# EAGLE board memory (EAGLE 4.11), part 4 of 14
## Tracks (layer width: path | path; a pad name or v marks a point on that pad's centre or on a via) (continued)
-IOP4  (via drill 0.61) (continued)
  Bottom 0.254: v22.23,277.5 24.13,279.4 v45.72,279.4 | v161.93,347.35 161.29,346.71 134.62,346.71 133.99,347.35 97.79,347.35 93.98,343.54 60.33,343.54 58.42,345.44 v55.88,345.44 29.21,345.44 v28.57,346.08 | v401.95,104.14 403.23,102.87 405.13,102.87 405.76,103.5 414.65,103.5 415.29,102.87 417.83,102.87 418.46,103.5 427.36,103.5 427.99,102.87 432.44,102.87 433.07,102.23 E06.N2 | v347.35,146.69 v398.78,146.69 | v347.35,143.51 345.44,141.6 321.31,141.6 320.68,142.24 304.8,142.24 304.17,141.6 255.91,141.6 254,143.51 238.76,143.51 236.22,140.97 147.32,140.97 144.78,143.51 119.38,143.51 118.11,142.24 104.14,142.24 103.5,142.88 102.87,142.88 101.6,141.6 50.16,141.6 48.9,140.34 v19.68,140.34
-IOT  (via drill 0.61)
  Top 0.254: v259.08,6.35 259.08,15.24 F20.U2 | v307.98,7.62 307.98,92.71 v307.34,93.34 | v297.18,139.7 297.81,140.34 297.81,151.13 297.18,151.76 D17.U2
  Route3 0.254: v312.42,139.7 314.32,137.79 314.32,99.69 v313.06,98.42
  Bottom 0.254: v259.08,6.35 259.71,6.98 276.23,6.98 276.86,7.62 v307.98,7.62 | v307.34,93.34 311.15,97.16 313.06,97.16 | 313.06,97.16 314.96,97.16 315.6,96.52 323.85,96.52 327.02,99.69 327.02,102.87 329.56,102.87 332.74,106.04 340.36,106.04 344.17,109.85 353.06,109.85 353.69,109.22 362.58,109.22 367.03,113.66 369.57,113.66 E11.J2 | v312.42,139.7 v297.18,139.7 | 313.06,97.16 v313.06,98.42
-IR00  (via drill 0.61)
  Route2 0.254: v283.21,179.07 287.65,179.07 288.29,179.7 292.74,179.7 293.37,180.34 D17.J2
  Route3 0.254: v260.35,149.86 260.35,179.07 259.08,180.34 259.08,183.51 D20.H2
  Bottom 0.254: v260.35,149.86 255.91,149.86 D20.V2 | v283.21,179.07 282.57,179.7 275.59,179.7 274.95,179.07 266.06,179.07 265.43,179.7 262.89,179.7 262.25,179.07 261.62,179.07 259.08,181.61 259.08,183.51 D20.H2
-IR01  (via drill 0.61)
  Top 0.254: v295.27,177.16 295.27,188.59 296.55,189.86 D17.E2
  Route2 0.254: D20.S2 258.44,159.38 257.18,160.66 257.18,170.18 261.62,170.18 265.43,173.99 267.97,173.99 D19.L2
  Bottom 0.254: v295.27,177.16 294,175.89 288.29,175.89 287.65,176.53 278.76,176.53 274.95,172.72 269.88,172.72 268.61,173.99 D19.L2
-IR02  (via drill 0.61)
  Top 0.254: v287.02,147.32 292.1,147.32 292.1,170.81 | 292.1,170.81 296.55,175.26 296.55,177.16 D17.K2 | v290.19,180.97 292.1,179.07 292.1,170.81
  Bottom 0.254: v287.02,147.32 269.88,147.32 268.61,148.59 D19.V2 | v290.19,180.97 288.29,182.88 287.02,182.88 286.38,182.25 277.5,182.25 276.86,182.88 272.42,182.88 271.78,183.51 D19.H2
-IR03  (via drill 0.61)
  Top 0.254: v277.5,186.06 279.4,187.96 v279.4,206.38 | v358.14,207.64 355.6,210.19 355.6,232.41 v356.87,233.68 | v290.19,287.02 290.19,274.96 288.93,273.69 288.93,252.09 v290.19,250.82 | v383.54,132.08 384.18,131.44 384.18,125.73 385.44,124.46 E10.E2
  Route2 0.254: v328.93,205.1 330.2,206.38 356.87,206.38 v358.14,207.64
  Route3 0.254: v274.32,158.75 276.23,160.66 276.23,184.78 v277.5,186.06 | v356.87,233.68 358.77,235.59 358.77,242.57 357.5,243.84 C12.L2 | v290.19,287.02 288.93,288.29 288.93,292.74 285.75,295.91 285.75,321.31 281.31,325.75 281.31,326.39 282.57,327.66 282.57,342.27 285.12,344.81 285.12,346.71 283.21,348.62 283.21,357.5 283.85,358.14 A18.U2 | v290.19,250.82 288.93,249.56 288.93,220.34 290.19,219.07 v290.19,206.38 | v383.54,132.08 384.18,132.72 v384.18,156.84 | v366.39,160.66 365.12,161.92 365.12,177.16 358.77,183.51 358.77,207.01 v358.14,207.64
  Bottom 0.254: v274.32,158.75 271.78,158.75 D19.S2 | v279.4,206.38 280.04,205.74 290.19,205.74 | 290.19,205.74 309.25,205.74 309.88,205.1 314.32,205.1 314.96,205.74 328.3,205.74 v328.93,205.1 | 290.19,205.74 v290.19,206.38 | v384.18,156.84 377.19,156.84 373.38,160.66 v366.39,160.66
-IRCLR  (via drill 0.61)
  Top 0.254: v252.73,173.35 250.82,175.26 v250.82,187.96 | v27.3,166.37 27.3,162.56 D38.R2 | v39.37,236.22 38.1,234.95 v38.1,191.13
  Route2 0.254: v27.3,166.37 31.75,170.81 31.75,186.69 27.3,186.69 D38.F2 | v39.37,236.22 42.55,236.22 42.55,240.66 C37.M2
  Bottom 0.254: 256.54,163.19 257.18,163.83 264.16,163.83 265.43,162.56 267.97,162.56 D19.R2 | 256.54,163.19 255.91,162.56 D20.R2 | D19.F2 267.97,187.96 263.52,187.96 262.25,189.23 261.62,189.23 260.99,188.59 256.54,188.59 255.91,187.96 D20.F2 255.27,187.32 251.46,187.32 v250.82,187.96 246.38,192.41 237.49,192.41 233.68,188.59 224.79,188.59 224.16,189.23 215.26,189.23 214.63,188.59 212.09,188.59 211.46,189.23 202.56,189.23 201.93,188.59 199.39,188.59 198.75,189.23 189.87,189.23 189.23,188.59 186.69,188.59 186.06,189.23 178.44,189.23 177.8,188.59 173.99,188.59 173.35,189.23 164.47,189.23 163.83,188.59 161.29,188.59 160.66,189.23 151.76,189.23 151.13,188.59 148.59,188.59 147.96,189.23 139.06,189.23 138.43,188.59 135.89,188.59 135.25,189.23 126.36,189.23 125.73,188.59 123.19,188.59 122.56,189.23 113.67,189.23 113.03,188.59 110.49,188.59 109.86,189.23 100.97,189.23 100.33,188.59 97.79,188.59 97.16,189.23 88.27,189.23 84.45,185.42 76.2,185.42 72.39,189.23 62.87,189.23 62.23,188.59 59.69,188.59 59.05,189.23 50.16,189.23 49.53,188.59 46.99,188.59 46.35,189.23 40.01,189.23 v38.1,191.13 36.83,192.41 34.29,192.41 29.84,187.96 27.3,187.96 D38.F2 | 256.54,163.19 254,165.73 254,173.35 v252.73,173.35
-IRSH  (via drill 0.61)
  Top 0.254: 269.88,172.09 268.61,170.81 268.61,168.91 D19.N2 | 269.88,172.09 271.14,173.35 271.14,177.16 D19.K2 271.14,178.44 269.88,179.7 269.88,188.59 268.61,189.86 268.61,193.04 D19.D2 | 269.88,172.09 269.88,154.31 271.14,153.03 D19.U2 | v236.22,307.98 238.12,306.07 v238.12,275.59 | v248.92,274.32 250.82,272.42 v250.82,194.31
  Route2 0.254: v236.22,307.98 233.68,307.98 B22.M2
  Route3 0.254: v259.08,173.35 259.08,177.16 D20.K2
  Bottom 0.254: D20.U2 259.08,153.03 263.52,153.03 264.8,154.31 267.97,154.31 269.24,153.03 271.14,153.03 D19.U2 | 262.25,170.18 264.16,170.18 265.43,168.91 267.97,168.91 D19.N2 | 262.25,170.18 257.18,170.18 255.91,168.91 D20.N2 | 262.25,170.18 v259.08,173.35 | v238.12,275.59 238.76,274.96 242.57,274.96 243.21,274.32 v248.92,274.32 | v250.82,194.31 251.46,193.67 255.27,193.67 D20.D2 255.91,194.31 258.44,194.31 259.71,195.58 262.25,195.58 262.89,194.94 267.33,194.94 267.97,194.31 D19.D2
-ISZ  (via drill 0.61)
  Top 0.254: v242.57,222.88 241.3,224.16 241.3,286.39 241.94,287.02 241.94,290.83 243.21,290.83 244.47,289.56 245.75,289.56 B21.U2 | v262.25,55.25 260.35,53.34 260.35,43.18 259.08,41.91 F20.K2 | v296.55,160.66 296.55,164.47 D17.P2 | v341.63,220.34 340.36,219.07 340.36,208.91 v341,208.28 | v295.91,217.81 v295.91,208.28
  Route2 0.254: v341.63,220.34 344.81,220.34 345.44,220.98 351.15,220.98 351.79,220.34 360.68,220.34 364.49,224.16 368.94,224.16 369.57,224.79 C11.T2
  Route3 0.254: v295.91,217.81 297.18,219.07 298.45,219.07 298.45,176.53 295.27,173.35 295.27,169.54 296.55,168.28 296.55,165.73 D17.P2 | v262.25,55.25 273.05,66.04 276.23,66.04 276.23,153.03 v280.67,157.48
  Bottom 0.254: v242.57,222.88 248.28,217.17 295.27,217.17 v295.91,217.81 | v280.67,157.48 283.21,160.02 289.56,160.02 290.19,160.66 v296.55,160.66 | v341,208.28 340.36,208.91 326.39,208.91 325.75,209.55 312.42,209.55 311.15,208.28 v295.91,208.28
-JMP  (via drill 0.61)
  Top 0.254: 158.75,107.31 v156.84,109.22 | v158.75,71.12 158.75,107.31 | v233.04,71.75 238.12,66.67 238.12,34.29 v247.01,25.4 | 158.75,107.31 v158.75,146.05
  Route2 0.254: v268.61,147.32 282.57,147.32 289.56,154.31 292.74,154.31 293.37,154.94 D17.T2 | v331.47,118.74 325.12,125.09 316.87,125.09 316.23,125.73 313.69,125.73 313.06,125.09 304.17,125.09 300.36,128.91 299.08,128.91 v297.18,127
  Route3 0.254: v385.44,107.95 385.44,105.41 E10.M2 | v297.18,127 295.27,128.91 295.27,138.43 292.74,140.97 292.74,143.51 293.37,144.14 293.37,147.32 292.1,148.59 292.1,153.67 293.37,154.94 D17.T2
  Bottom 0.254: F16.R2 306.07,24.77 303.53,24.77 302.26,23.49 299.72,23.49 299.08,24.13 290.19,24.13 288.93,22.86 287.65,22.86 285.12,20.32 277.5,20.32 276.86,20.95 274.32,20.95 273.69,20.32 264.8,20.32 264.16,20.95 259.71,20.95 259.08,21.59 F20.S2 258.44,22.86 254.63,22.86 253.37,24.13 252.09,24.13 251.46,23.49 248.92,23.49 v247.01,25.4 | v156.84,109.22 150.5,109.22 149.86,109.85 145.41,109.85 144.78,110.49 E29.K2 | v158.75,71.12 188.59,71.12 189.87,69.85 191.13,69.85 193.04,71.75 210.82,71.75 211.46,72.39 230.5,72.39 231.78,71.12 232.41,71.12 v233.04,71.75 | v268.61,147.32 240.66,147.32 236.85,151.13 227.97,151.13 227.33,150.5 224.79,150.5 224.16,151.13 215.26,151.13 214.63,150.5 212.09,150.5 211.46,151.13 202.56,151.13 201.93,150.5 199.39,150.5 198.75,151.13 196.22,151.13 190.5,145.41 159.38,145.41 v158.75,146.05 | v385.44,107.95 384.18,109.22 377.19,109.22 374.01,112.39 372.75,112.39 371.48,113.66 371.48,115.57 366.39,115.57 362.58,119.38 356.24,119.38 353.06,122.55 350.52,122.55 345.44,117.47 345.44,115.57 339.09,115.57 338.45,116.2 334.01,116.2 v331.47,118.74
-JMS  (via drill 0.61)
  Top 0.254: v255.27,275.59 255.27,283.85 254,285.12 254,292.74 255.27,294 255.27,297.81 B20.R2 | v260.35,9.52 v260.35,13.97 260.35,26.67 259.08,27.94 F20.P2 | v317.5,9.52 317.5,36.2 318.77,37.46 F15.L2 | v142.88,62.87 142.88,106.04 141.6,107.31 E29.L2 | v189.23,156.21 187.32,154.31 v187.32,147.95 | v162.56,147.32 161.93,146.69 v161.93,114.3
  Route2 0.254: v281.31,160.02 287.65,160.02 288.29,160.66 295.27,160.66 296.55,159.38 D17.S2
  Route3 0.254: v301.62,273.05 301.62,227.97 304.8,224.79 304.8,187.96 301.62,184.78 301.62,161.29 v300.36,160.02 | v142.88,62.87 142.88,59.69 v189.87,12.7
  Bottom 0.254: v255.27,275.59 255.91,276.23 269.24,276.23 270.51,274.96 299.72,274.96 v301.62,273.05 | v300.36,160.02 297.81,160.02 297.18,159.38 D17.S2 | v260.35,9.52 306.07,9.52 306.7,10.16 316.87,10.16 v317.5,9.52 | v189.87,12.7 192.41,10.16 201.29,10.16 201.93,10.79 213.36,10.79 217.17,14.61 226.06,14.61 226.69,13.97 227.33,13.97 227.97,14.61 234.31,14.61 234.95,15.24 238.12,15.24 239.4,13.97 248.28,13.97 248.92,14.61 251.46,14.61 252.09,13.97 v260.35,13.97 | v281.31,160.02 278.13,156.84 275.59,156.84 274.95,157.48 266.06,157.48 262.25,153.67 253.37,153.67 252.73,154.31 250.19,154.31 249.56,153.67 248.28,153.67 245.11,156.84 237.49,156.84 236.85,157.48 227.97,157.48 227.33,156.84 224.79,156.84 224.16,157.48 215.26,157.48 214.63,156.84 212.09,156.84 211.46,157.48 202.56,157.48 201.93,156.84 199.39,156.84 198.75,157.48 190.5,157.48 v189.23,156.21 | v187.32,147.95 186.06,146.69 163.19,146.69 v162.56,147.32 | v161.93,114.3 161.93,112.39 151.76,112.39 151.13,113.03 148.59,113.03 147.96,112.39 143.51,112.39 141.6,110.49 141.6,108.58 E29.L2
-L  (via drill 0.61)
  Route2 0.254: v446.4,234.31 439.42,241.3 438.79,241.3 421.64,258.44 421,258.44 421,262.89 C07.D2 | v454.02,182.88 454.02,176.53 452.12,176.53 447.68,172.09 447.68,156.84 445.13,156.84 437.51,149.22 437.51,139.7 441.32,135.89 v441.32,111.76
  Route3 0.254: v446.4,234.31 447.68,233.04 447.68,227.33 454.02,220.98 454.02,205.74 452.75,204.47 452.75,201.93 454.02,200.66 v454.02,182.88 | v441.32,111.76 441.32,72.39 438.15,69.22 438.15,55.88 436.88,54.61 F06.E2
  Bottom 0.254: F03.H2 474.35,46.99 473.07,45.72 466.09,45.72 462.28,49.53 455.93,49.53 452.75,52.7 443.87,52.7 443.23,52.07 441.96,52.07 440.69,53.34 436.88,53.34 F06.E2
-LAS  (via drill 0.61)
  Top 0.254: v257.81,296.55 257.18,297.18 257.18,311.79 256.54,312.42 256.54,316.23 257.18,316.87 257.18,323.85 259.08,325.75 259.08,326.39 B20.E2
  Route2 0.254: v481.33,306.07 474.98,299.72 467.36,299.72 v465.45,301.62 | v433.07,300.36 426.08,293.37 415.29,293.37 411.48,297.18 402.59,297.18 401.95,296.55 393.06,296.55 392.43,297.18 389.89,297.18 389.25,296.55 387.99,296.55 386.08,298.45 381,293.37 377.19,293.37 376.56,294 367.67,294 367.03,293.37 364.49,293.37 363.86,294 357.5,294 356.87,293.37 354.33,293.37 351.15,290.2 342.26,290.2 341.63,290.83 339.09,290.83 335.28,287.02 326.39,287.02 325.75,287.66 316.87,287.66 316.23,287.02 313.69,287.02 313.06,287.66 304.17,287.66 303.53,287.02 302.26,287.02 295.91,293.37 288.29,293.37 287.65,294 278.76,294 278.13,293.37 275.59,293.37 274.32,294.64 271.78,294.64 B19.S2
  Bottom 0.254: v257.81,296.55 262.25,296.55 262.89,297.18 269.88,297.18 271.14,295.91 B19.S2 | v481.33,306.07 487.68,306.07 491.49,309.88 495.94,309.88 496.57,310.52 B01.L2 | v465.45,301.62 464.82,300.99 463.55,300.99 462.92,300.36 456.56,300.36 455.93,299.72 453.39,299.72 452.75,300.36 445.13,300.36 444.5,299.72 440.69,299.72 440.06,300.36 v433.07,300.36
-LCIF  (via drill 0.61)
  Route3 0.254: v55.24,93.98 58.42,97.16 58.42,98.42 69.85,109.85 69.85,205.74 66.67,208.91 66.67,294.64 63.5,297.81 v63.5,307.34
  Bottom 0.254: v55.24,93.98 48.26,86.99 40.01,86.99 40.01,83.18 E37.V2 | v63.5,307.34 65.41,309.25 73.66,309.25 74.93,310.52 77.47,310.52 B34.L2
-LD  (via drill 0.61)
  Top 0.254: v361.95,342.27 361.95,397.51 358.14,401.32 352.43,401.32 352.43,399.42 349.25,396.24 347.98,396.24 A13.E2 347.35,397.51 346.07,398.78 346.07,400.69 335.28,411.48 v334.64,411.48 | 28.57,223.52 27.3,224.79 C38.T2 | 28.57,223.52 v28.57,209.55 | v137.79,209.55 139.7,207.64 v139.7,168.28 | v62.23,317.5 60.33,315.6 60.33,297.18 v55.88,292.74 | v34.92,285.12 33.66,283.85 v33.66,273.69 | v26.67,234.95 28.57,233.04 28.57,223.52 | v250.82,408.94 250.82,412.75 253.37,415.29 252.09,416.56 196.85,416.56 196.85,408.31 193.68,405.13 v193.68,393.06 | v128.91,349.89 120.65,341.63 120.65,338.46 v112.39,330.2
  Route2 0.254: v62.23,317.5 63.5,318.77 66.67,318.77 67.94,320.04 B35.H2 68.58,321.31 71.12,321.31 75.56,325.75 84.45,325.75 85.09,325.12 87.63,325.12 88.27,325.75 97.16,325.75 97.79,325.12 101.6,325.12 108.58,332.11 110.49,332.11 v112.39,330.2 | v33.66,273.69 25.4,265.43 25.4,234.95 v26.67,234.95 | v193.68,393.06 193.68,386.08 186.69,386.08 182.88,382.27 173.99,382.27 173.35,382.91 164.47,382.91 163.83,382.27 161.29,382.27 160.66,382.91 158.12,382.91 154.94,379.73 154.31,379.73 v152.4,377.83
  Route3 0.254: v343.54,339.73 336.55,332.74 336.55,328.93 335.28,327.66 B14.E2 | v334.64,411.48 327.66,418.47 260.35,418.47 260.35,417.83 254,411.48 254,408.94 252.73,407.67 250.82,407.67 v250.82,408.94 | v152.4,377.83 152.4,377.19 128.91,353.7 v128.91,349.89
  Bottom 0.254: v343.54,339.73 346.07,342.27 v361.95,342.27 | v28.57,209.55 29.21,208.91 36.2,208.91 36.83,208.28 67.31,208.28 68.58,209.55 74.3,209.55 75.56,208.28 96.52,208.28 98.42,210.19 113.67,210.19 114.3,209.55 v137.79,209.55 | v139.7,168.28 139.7,165.73 144.15,165.73 D29.P2 | v55.88,292.74 53.98,290.83 48.26,290.83 44.45,287.02 38.73,287.02 36.83,285.12 v34.92,285.12
-LP  (via drill 0.61)
  Top 0.254: v57.15,356.24 57.15,394.97 55.88,396.24 A36.E2 | v273.05,352.43 273.05,382.27 271.78,383.54 A19.K2 271.14,384.81 271.14,388.62 269.88,389.89 v269.88,415.29 | v343.54,351.79 342.9,352.43 342.9,360.05 344.17,361.31 A13.T2 | v328.93,350.52 328.93,346.08 330.2,344.81 330.2,294 331.47,292.74 B14.T2 | v88.27,400.05 104.14,415.93 146.69,415.93 146.69,414.66 v147.96,413.39
  Bottom 0.254: 57.15,353.7 152.4,353.7 153.67,354.97 A28.V2 | 57.15,353.7 41.27,353.7 40.01,354.97 A37.V2 | v57.15,356.24 57.15,353.7 | B19.T2 268.61,292.74 273.05,292.74 274.32,294 276.86,294 277.5,293.37 286.38,293.37 287.02,294 289.56,294 293.37,290.2 300.36,290.2 304.17,294 314.96,294 315.6,293.37 324.49,293.37 325.12,294 326.39,294 328.3,292.1 331.47,292.1 B14.T2 | v273.05,352.43 290.83,352.43 294,349.25 323.85,349.25 324.49,349.89 328.93,349.89 | 328.93,349.89 339.73,349.89 341.63,351.79 v343.54,351.79 | 328.93,349.89 v328.93,350.52 | v88.27,400.05 86.36,398.15 83.82,398.15 83.19,398.78 74.3,398.78 73.66,398.15 71.12,398.15 70.48,398.78 61.59,398.78 60.96,398.15 56.52,398.15 55.88,397.51 A36.E2 | v147.96,413.39 154.31,413.39 155.57,414.66 161.93,414.66 162.56,415.29 192.41,415.29 193.68,416.56 252.09,416.56 253.37,415.29 v269.88,415.29
-LPA  (via drill 0.61)
  Top 0.254: v27.3,328.3 27.3,324.49 B38.F2 | v201.93,392.43 198.75,395.61 v198.75,398.15 | v69.22,388.62 63.5,382.91 63.5,376.56 64.77,375.29 A35.N2
  Route2 0.254: v27.3,328.3 28.57,329.56 28.57,334.01 64.14,369.57 64.77,369.57 64.77,374.02 A35.N2 | v179.71,401.96 179.07,401.32 173.99,401.32 173.35,401.96 164.47,401.96 160.66,398.15 151.76,398.15 142.24,407.67 137.16,407.67 133.35,411.48 92.08,411.48 v69.22,388.62
  Bottom 0.254: B38.F2 26.67,323.22 26.67,320.04 25.4,318.77 25.4,315.6 35.56,315.6 36.2,316.23 45.09,316.23 45.72,315.6 48.26,315.6 48.9,316.23 57.78,316.23 58.42,315.6 60.96,315.6 61.59,316.23 64.77,316.23 66.04,314.96 67.94,314.96 B35.K2 | v201.93,392.43 208.28,392.43 215.26,385.45 224.16,385.45 227.97,389.25 236.85,389.25 237.49,388.62 240.03,388.62 240.66,389.25 249.56,389.25 250.19,388.62 254.63,388.62 255.27,387.99 A20.J2 | v198.75,398.15 189.87,398.15 186.06,401.96 v179.71,401.96
-LPC  (via drill 0.61)
  Top 0.254: E05.U2 448.94,86.36 447.68,87.63 447.68,89.53 446.4,90.8 446.4,94.61 E05.R2 | C40.M2 5.08,241.94 6.35,243.2 6.35,276.86 5.08,278.13 5.08,287.02 6.35,288.29 6.35,366.4 5.08,367.67 5.08,370.84 A40.P2
  Route2 0.254: v337.82,85.72 335.92,83.82 328.93,83.82 325.75,80.64 318.13,80.64 311.15,87.63 304.17,87.63 295.27,96.52 288.29,96.52 281.94,102.87 275.59,102.87 274.95,103.5 266.06,103.5 265.43,102.87 264.16,102.87 v259.08,107.95 | v234.31,103.5 233.68,102.87 224.79,102.87 224.16,103.5 217.81,103.5 214.63,106.68 212.09,106.68 211.46,106.04 210.82,106.04 209.55,107.31 209.55,109.85 207.01,109.85 170.81,146.05 160.66,146.05 153.67,153.03 152.4,153.03 151.13,154.31 148.59,154.31 v142.88,148.59 | v71.75,152.4 53.98,170.18 53.98,201.29 46.99,201.29 8.26,240.03 5.71,240.03 5.08,240.66 C40.M2
  Route3 0.254: v408.31,90.8 404.5,94.61 v404.5,95.25
  Bottom 0.254: v408.31,90.8 415.93,90.8 422.27,84.45 427.36,84.45 427.99,83.82 430.53,83.82 431.17,84.45 440.06,84.45 440.69,83.82 447.68,83.82 448.94,85.09 E05.U2 | v404.5,95.25 402.59,93.34 395.61,93.34 392.43,90.17 390.52,90.17 387.35,93.34 380.37,93.34 379.73,93.98 377.19,93.98 376.56,93.34 367.67,93.34 367.03,93.98 365.76,93.98 363.22,91.44 361.95,91.44 360.68,90.17 351.79,90.17 351.15,90.8 343.54,90.8 338.45,85.72 v337.82,85.72 | v259.08,107.95 257.81,109.22 252.73,109.22 246.38,102.87 237.49,102.87 236.85,103.5 v234.31,103.5 | v142.88,148.59 141.6,147.32 100.33,147.32 99.69,146.69 82.55,146.69 78.74,150.5 73.66,150.5 v71.75,152.4
-LSH  (via drill 0.61)
  Top 0.254: F03.D2 471.81,56.52 473.07,55.25 473.07,46.36 474.35,45.09 474.35,41.91 F03.K2 | v160.02,300.99 161.93,302.9 161.93,310.52 165.1,313.69 v165.1,314.33 | v392.43,161.29 390.52,163.19 390.52,189.23 v389.25,190.5
  Route2 0.254: v457.2,137.16 457.2,140.34 450.85,140.34 v443.23,147.95 | v404.5,155.57 402.59,153.67 400.05,153.67 v392.43,161.29 | v393.7,229.23 388.62,234.31 387.35,234.31 386.08,233.04 379.1,233.04 372.75,239.39 366.39,239.39 v360.05,245.75 | v185.42,314.33 183.51,312.42 173.99,312.42 172.72,313.69 170.18,313.69 B27.K2
  Route3 0.254: v457.2,137.16 457.2,81.91 466.73,72.39 466.73,57.79 471.17,57.79 F03.D2 | v389.25,190.5 390.52,191.77 390.52,198.12 392.43,200.03 393.7,200.03 393.7,199.39 394.33,198.75 396.88,198.75 396.88,199.39 400.05,202.56 400.05,212.72 398.78,214 398.78,217.81 400.05,219.07 400.05,222.88 v393.7,229.23 | v360.05,245.75 355.6,250.19 355.6,278.77 358.77,281.94 358.77,312.42 351.79,319.41 351.79,320.68 349.25,323.22 349.25,350.52 347.98,351.79 347.98,356.87 349.25,358.14 349.25,372.75 v337.82,384.18 | v288.93,386.72 287.65,385.45 278.76,385.45 274.95,389.25 266.06,389.25 262.25,385.45 257.18,385.45 257.18,387.99 249.56,395.61 240.66,395.61 233.68,388.62 225.43,388.62 225.43,384.81 213.36,372.75 203.2,372.75 203.2,363.22 200.03,360.05 200.03,346.71 187.32,334.01 187.32,328.3 184.15,325.12 184.15,315.6 v185.42,314.33
  Bottom 0.254: v160.02,300.99 158.75,299.72 149.22,299.72 142.88,306.07 137.79,306.07 137.16,306.71 132.72,306.71 132.08,307.34 B30.M2 | v165.1,314.33 169.54,314.33 B27.K2 | v443.23,147.95 434.34,156.84 427.99,156.84 427.36,157.48 418.46,157.48 414.65,153.67 412.12,153.67 408.94,156.84 405.76,156.84 v404.5,155.57 | v337.82,384.18 335.92,386.08 326.39,386.08 325.75,385.45 316.87,385.45 316.23,386.08 313.69,386.08 310.51,382.91 306.7,382.91 303.53,386.08 302.26,386.08 299.72,383.54 298.45,383.54 297.81,382.91 294,382.91 290.19,386.72 v288.93,386.72
-MA00  (via drill 0.61)
  Top 0.254: v215.9,55.25 214.63,56.52 214.63,58.42 215.9,59.69 v215.9,76.83 v215.9,82.55 | v316.87,78.1 317.5,78.74 317.5,97.79 | 317.5,97.79 317.5,112.39 318.77,113.66 E15.J2 | v224.16,146.05 223.52,145.41 223.52,135.25 222.25,133.99 222.25,114.3 v220.98,113.03 | 317.5,97.79 v318.13,97.79
  Route2 0.254: v318.13,97.79 321.94,97.79 E15.P2
  Route3 0.254: v242.57,146.05 244.47,147.95 244.47,188.59 245.75,189.86 D21.E2 | v220.98,113.03 222.25,111.76 222.25,90.8 215.9,84.45 v215.9,82.55
  Bottom 0.254: v215.9,55.25 215.26,55.88 214,55.88 213.36,55.25 208.91,55.25 208.28,54.61 F24.E2 | v215.9,76.83 216.53,76.2 264.8,76.2 266.06,74.93 267.33,76.2 267.33,76.83 283.85,76.83 285.12,78.1 v316.87,78.1 | v224.16,146.05 v242.57,146.05
-MA00B  (via drill 0.61)
  Top 0.254: v382.9,28.58 382.9,31.12 F10.N2 | v386.71,29.84 390.52,26.03 390.52,12.06 v387.35,8.89 | v298.45,4.44 291.46,11.43 v290.83,11.43 | v266.7,12.06 263.52,15.24 263.52,27.94 254,37.46 254,43.82 v252.09,45.72
  Route2 0.254: v382.9,28.58 384.18,29.84 v386.71,29.84 | v387.35,8.89 386.71,9.52 373.38,9.52 367.67,3.81 340.36,3.81 339.73,4.44 339.09,4.44 337.82,3.17 299.72,3.17 v298.45,4.44 | v252.09,45.72 245.75,52.07 237.49,52.07 231.14,58.42 224.79,58.42 220.98,62.23 212.09,62.23 211.46,61.59 202.56,61.59 198.75,65.41 192.41,65.41 189.23,68.58 166.37,68.58 165.74,67.94 164.47,67.94 162.56,69.85 137.16,69.85 134.62,72.39 116.2,72.39 v90.17,98.42 | v88.27,257.18 v71.75,273.69
  Route3 0.254: v290.83,11.43 288.29,11.43 287.02,10.16 266.7,10.16 v266.7,12.06 | v90.17,98.42 88.9,99.69 88.9,182.25 92.08,185.42 92.08,253.36 v88.27,257.18 | v71.75,273.69 69.85,275.59 69.85,302.26 66.67,305.44 66.67,359.41 65.41,360.68 65.41,361.31 A35.T2
-MA01  (via drill 0.61)
  Top 0.254: v226.69,49.53 228.6,51.44 v228.6,67.94 | v299.72,69.22 302.89,72.39 v302.89,74.29 | v319.4,73.66 319.4,80.64 320.68,81.91 320.68,86.36 319.4,87.63 319.4,88.27 E15.T2 | v309.88,119.38 309.88,123.19 E16.E2 | v239.4,180.97 241.3,179.07 v241.3,142.24 | v304.8,123.82 v304.8,140.97
  Route3 0.254: v252.73,68.58 255.27,68.58 v255.27,69.22 | v309.88,119.38 311.15,118.11 311.15,99.06 318.77,91.44 318.77,89.53 E15.T2
  Bottom 0.254: v226.69,49.53 226.06,48.9 223.52,48.9 222.88,49.53 214,49.53 213.36,48.9 208.91,48.9 208.28,48.26 F24.H2 | v228.6,67.94 229.24,68.58 238.12,68.58 238.76,69.22 252.09,69.22 v252.73,68.58 | v255.27,69.22 256.54,70.48 295.91,70.48 297.18,69.22 v299.72,69.22 | v302.89,74.29 303.53,73.66 310.51,73.66 311.15,73.02 318.77,73.02 v319.4,73.66 | v239.4,180.97 240.03,180.97 241.3,182.25 244.47,182.25 245.75,183.51 D21.H2 | v241.3,142.24 254,142.24 255.27,140.97 v304.8,140.97 | v304.8,123.82 309.25,123.82 E16.E2
-MA01B  (via drill 0.61)
  Top 0.254: v22.23,319.41 22.23,367.03 v24.13,368.94
  Route2 0.254: v290.19,45.72 283.85,52.07 275.59,52.07 274.95,52.7 268.61,52.7 267.97,52.07 264.16,52.07 260.35,55.88 254,55.88 235.59,74.29 211.46,74.29 v210.19,75.56 | v175.9,76.83 162.56,76.83 161.93,76.2 126.36,76.2 v81.28,121.28 | v67.94,250.19 34.29,283.85 33.02,283.85 v23.5,293.37
  Route3 0.254: v382.27,47.62 382.27,45.09 F10.J2 | v81.28,121.28 79.38,123.19 79.38,144.78 76.2,147.95 76.2,208.91 69.85,215.26 69.85,248.28 v67.94,250.19 | v23.5,293.37 22.23,294.64 v22.23,319.41
  Bottom 0.254: v382.27,47.62 380.37,49.53 377.19,49.53 376.56,48.9 367.67,48.9 367.03,49.53 364.49,49.53 363.86,48.9 354.96,48.9 354.33,49.53 351.79,49.53 351.15,48.9 342.26,48.9 341.63,49.53 339.09,49.53 338.45,48.9 329.56,48.9 328.93,49.53 326.39,49.53 325.75,48.9 316.87,48.9 316.23,49.53 313.69,49.53 313.06,48.9 304.17,48.9 303.53,49.53 302.89,49.53 299.08,45.72 v290.19,45.72 | v210.19,75.56 207.01,75.56 206.38,74.93 201.93,74.93 198.75,78.1 184.15,78.1 182.88,76.83 v175.9,76.83 | v24.13,368.94 17.78,375.29 17.78,377.19 A39.M2
-MA02  (via drill 0.61)
  Top 0.254: v299.72,76.83 304.8,81.91 v304.8,97.16 | F24.K2 207.65,41.91 206.38,43.18 v206.38,76.2 v206.38,99.06 | E16.J2 306.7,113.66 306.7,109.85 307.98,108.58 307.98,104.14 309.25,102.87 309.25,99.06 E16.P2 | v208.28,161.92 206.38,160.02 206.38,110.49 208.28,108.58 v208.28,107.95
  Route2 0.254: v242.57,177.8 221.62,156.84 213.36,156.84 v208.28,161.92
  Route3 0.254: v208.28,107.95 206.38,106.04 v206.38,99.06
  Bottom 0.254: v206.38,76.2 207.01,76.83 214.63,76.83 215.9,75.56 264.16,75.56 265.43,74.29 266.7,74.29 268.61,76.2 284.48,76.2 285.75,77.47 299.08,77.47 v299.72,76.83 | v304.8,97.16 306.07,98.42 309.25,98.42 E16.P2 | v242.57,177.8 245.75,177.8 D21.K2
-MA02B  (via drill 0.61)
  Top 0.254: v370.2,15.24 360.68,5.71 349.25,5.71 v349.25,12.7 | v74.93,114.3 73.03,116.2 v73.03,123.82
  Route2 0.254: v349.25,12.7 347.98,13.97 339.09,13.97 338.45,14.61 337.82,14.61 v336.55,13.34 | v318.77,14.61 318.13,13.97 313.69,13.97 313.06,14.61 304.17,14.61 303.53,13.97 300.99,13.97 297.18,17.78 292.74,17.78 v291.46,19.05 | v269.88,40.64 264.16,46.36 257.18,46.36 255.27,48.26 254,48.26 249.56,52.7 244.47,52.7 234.95,62.23 227.33,62.23 220.98,68.58 200.66,68.58 200.03,67.94 194.94,67.94 193.04,69.85 166.37,69.85 163.19,73.02 116.84,73.02 75.56,114.3 v74.93,114.3 | v71.12,160.02 57.15,173.99 57.15,208.28 48.26,208.28 22.23,234.31 22.23,276.23 21.59,276.23 9.53,288.29 9.53,333.38 8.26,334.65 15.88,342.27 15.88,380.37 14.61,380.37 A39.L2
  Route3 0.254: v370.2,15.24 370.2,14.61 375.92,14.61 381,19.69 381,23.49 382.27,24.77 F10.R2 | v291.46,19.05 274.32,36.2 269.88,36.2 v269.88,40.64 | v73.03,123.82 73.03,142.24 74.3,143.51 74.3,148.59 73.03,149.86 73.03,158.11 v71.12,160.02
  Bottom 0.254: v336.55,13.34 335.92,13.97 326.39,13.97 325.75,14.61 v318.77,14.61
-MA03  (via drill 0.61)
  Top 0.254: v219.07,78.1 v219.07,36.83 | v306.07,86.36 306.07,88.27 E16.T2 | v297.18,119.38 297.18,123.19 E17.E2 296.55,124.46 295.27,125.73 v295.27,139.7 | v252.09,161.29 254,159.38 v254,140.97
  Route3 0.254: v297.18,119.38 298.45,118.11 298.45,87.63 v300.36,85.72
  Bottom 0.254: v219.07,36.83 214,36.83 213.36,36.2 208.91,36.2 208.28,35.56 F24.M2 | v219.07,78.1 220.98,80.01 243.84,80.01 244.47,80.64 246.38,80.64 248.28,78.74 280.67,78.74 281.94,80.01 294.64,80.01 295.27,80.64 300.36,80.64 302.89,83.18 | 302.89,83.18 v306.07,86.36 | 302.89,83.18 v300.36,85.72 | v252.09,161.29 247.01,166.37 246.38,166.37 246.38,170.81 D21.M2 | v254,140.97 254.63,140.34 294.64,140.34 v295.27,139.7
-MA03B  (via drill 0.61)
  Route2 0.254: v132.72,9.52 203.2,9.52 205.74,6.98 249.56,6.98 v250.82,5.71
  Route3 0.254: v4.45,199.39 3.17,200.66 3.17,273.69 3.81,274.32 3.81,278.13 9.53,283.85 9.53,330.84 8.26,332.11 8.26,334.65 9.53,335.92 9.53,367.67 13.97,367.67 A39.R2 | v11.43,173.35 12.7,172.09 12.7,144.78 13.97,143.51 13.97,135.25 12.7,133.99 12.7,54.61 47.62,19.69 47.62,15.24 54.61,8.25 132.72,8.25 v132.72,9.52 | v250.82,5.71 254.63,1.9 285.12,1.9 285.75,2.54 327.02,2.54 328.93,0.63 374.01,0.63 374.01,5.08 375.92,6.98 386.08,6.98 386.71,6.35 390.52,6.35 390.52,20.32 384.18,26.67 384.18,36.2 382.9,37.46 F10.L2
  Bottom 0.254: v4.45,199.39 1.91,196.85 1.91,194.94 2.54,194.94 3.17,194.31 3.17,172.72 10.16,172.72 10.79,173.35 v11.43,173.35
-MA04  (via drill 0.61)
  Top 0.254: v212.72,75.56 v212.72,29.21 | v292.1,76.2 v292.1,98.42 | E17.J2 294,113.66 295.27,112.39 295.27,104.14 296.55,102.87 296.55,99.06 E17.P2 | v83.82,351.16 85.72,349.25 v85.72,283.85 | v149.22,215.26 v149.22,283.85 | v220.34,215.26 220.98,214.63 v220.98,206.38 | v238.12,174.62 v238.12,206.38 | v281.31,116.2 280.67,116.84 280.67,118.74 279.4,120.02 v279.4,137.79
  Route2 0.254: v212.72,29.21 208.28,29.21 F24.P2
  Route3 0.254: v20.95,351.79 19.05,353.7 19.05,369.57 17.78,370.84 A39.P2 | v249.56,137.79 247.65,139.7 247.65,160.02 246.38,161.29 246.38,164.47 D21.P2
  Bottom 0.254: v212.72,75.56 213.36,74.93 263.52,74.93 264.8,73.66 267.33,73.66 269.24,75.56 285.12,75.56 285.75,76.2 v292.1,76.2 | v292.1,98.42 296.55,98.42 E17.P2 | v20.95,351.79 22.23,350.52 58.42,350.52 59.05,351.16 v83.82,351.16 | v85.72,283.85 86.36,283.21 148.59,283.21 v149.22,283.85 | v149.22,215.26 172.09,215.26 172.72,215.9 219.71,215.9 v220.34,215.26 | v238.12,206.38 v220.98,206.38 | v238.12,174.62 238.12,170.81 243.21,165.73 245.75,165.73 D21.P2 | v281.31,116.2 287.65,116.2 288.93,114.93 293.37,114.93 E17.J2 | v279.4,137.79 278.76,138.43 250.19,138.43 v249.56,137.79
-MA05  (via drill 0.61)
  Top 0.254: v223.52,23.49 224.16,23.49 225.43,24.77 v225.43,78.1 | v295.27,79.38 295.27,83.82 294,85.09 294,88.27 E17.T2 | v244.47,79.38 244.47,138.43 | 244.47,138.43 244.47,153.03 245.11,153.67 245.11,157.48 245.75,158.11 D21.S2 | v282.57,137.79 282.57,125.73 283.85,124.46 E18.E2 | 244.47,138.43 v246.38,138.43
  Bottom 0.254: v223.52,23.49 222.88,24.13 214,24.13 213.36,23.49 208.91,23.49 208.28,22.86 F24.S2 | v225.43,78.1 226.69,79.38 v244.47,79.38 246.38,79.38 247.65,78.1 281.31,78.1 282.57,79.38 v295.27,79.38 | v282.57,137.79 281.31,139.06 247.01,139.06 v246.38,138.43
-MA06  (via drill 0.61)
  Top 0.254: v209.55,74.29 209.55,17.78 208.28,16.51 F24.U2 | v285.75,74.93 285.75,95.25 284.48,96.52 284.48,97.79 E18.P2 283.85,99.06 283.85,102.87 282.57,104.14 282.57,108.58 281.94,109.22 281.94,113.03 281.31,113.66 E18.J2 | v239.4,160.66 239.4,162.56 234.95,167 234.95,188.59 233.68,189.86 D22.E2
  Route2 0.254: v243.21,124.46 243.84,125.09 251.46,125.09 252.09,125.73 260.99,125.73 267.33,119.38 273.69,119.38 278.76,114.3 280.67,114.3 E18.J2
  Route3 0.254: v239.4,160.66 238.12,159.38 238.12,146.69 240.03,144.78 240.03,138.43 241.3,137.16 241.3,126.36 v243.21,124.46
  Bottom 0.254: v209.55,74.29 262.89,74.29 264.16,73.02 267.97,73.02 269.88,74.93 v285.75,74.93
-MA07  (via drill 0.61)
  Top 0.254: v190.5,53.34 191.77,54.61 191.77,55.25 190.5,56.52 190.5,69.22 v195.58,74.29 | v282.57,78.1 282.57,86.99 281.31,88.27 E18.T2 | v285.75,96.52 v285.75,121.92 | v263.52,157.48 263.52,146.69 v265.43,144.78 | v267.97,144.14 269.88,142.24 269.88,125.73 271.14,124.46 E19.E2
  Route2 0.254: v265.43,144.78 266.06,144.14 v267.97,144.14
  Route3 0.254: v245.11,73.02 246.38,74.29 v246.38,78.1 | v285.75,96.52 282.57,96.52 282.57,93.98 281.31,92.71 281.31,89.53 E18.T2 | v237.49,170.18 234.95,172.72 234.95,182.25 233.68,183.51 D22.H2
  Bottom 0.254: v190.5,53.34 194.94,53.34 F25.E2 | v195.58,74.29 196.85,73.02 209.55,73.02 210.19,73.66 244.47,73.66 v245.11,73.02 | v246.38,78.1 247.01,77.47 281.94,77.47 v282.57,78.1 | v285.75,121.92 277.5,121.92 276.86,122.55 272.42,122.55 271.78,123.19 E19.E2 | v237.49,170.18 250.82,156.84 260.99,156.84 261.62,157.48 v263.52,157.48
-MA08  (via drill 0.61)
  Top 0.254: v193.68,66.67 193.68,49.53 194.94,48.26 F25.H2 | v263.52,67.94 v263.52,92.07 | E19.J2 268.61,113.66 269.88,112.39 269.88,104.14 271.14,102.87 271.14,99.06 E19.P2
  Route3 0.254: v248.92,177.8 247.65,176.53 247.65,161.29 250.82,158.11 250.82,127.63 254,124.46 v254,120.65
  Bottom 0.254: v193.68,66.67 193.68,67.94 200.66,67.94 201.29,68.58 227.97,68.58 228.6,69.22 237.49,69.22 238.12,69.85 252.73,69.85 254.63,67.94 v263.52,67.94 | v263.52,92.07 263.52,96.52 269.88,96.52 271.14,97.79 E19.P2 | v248.92,177.8 247.01,179.7 239.4,179.7 238.76,179.07 234.31,179.07 233.68,178.44 D22.K2 | v254,120.65 254,118.74 264.16,118.74 264.8,119.38 265.43,119.38 267.97,116.84 268.61,116.84 270.51,118.74 272.42,118.74 273.05,118.11 273.05,114.93 268.61,114.93 E19.J2
-MA09  (via drill 0.61)
  Top 0.254: D22.M2 233.68,170.81 233.68,167 238.12,162.56 v238.12,121.92 v238.12,77.47 | v201.29,43.82 203.2,45.72 v203.2,78.1 | v266.06,76.2 266.7,76.83 266.7,86.99 267.97,88.27 E19.T2
  Bottom 0.254: v238.12,121.92 240.03,121.92 240.66,122.55 249.56,122.55 250.19,121.92 257.18,121.92 258.44,123.19 E20.E2 | v201.29,43.82 200.03,42.55 196.22,42.55 195.58,41.91 F25.K2 | v203.2,78.1 217.81,78.1 219.07,76.83 238.12,76.83 | 238.12,76.83 265.43,76.83 v266.06,76.2 | 238.12,76.83 v238.12,77.47
-MA10  (via drill 0.61)
  Top 0.254: v198.75,34.92 200.03,36.2 v200.03,69.22 | 254,97.79 254,112.39 255.27,113.66 E20.J2 | v254,69.85 254,97.79 | v234.95,114.93 234.95,163.19 233.68,164.47 D22.P2 | 254,97.79 v255.27,97.79
  Route2 0.254: v198.75,34.92 195.58,34.92 F25.M2
  Bottom 0.254: v200.03,69.22 227.33,69.22 227.97,69.85 236.85,69.85 237.49,70.48 253.37,70.48 v254,69.85 | v234.95,114.93 234.95,112.39 238.76,112.39 239.4,113.03 248.28,113.03 248.92,112.39 251.46,112.39 253.37,114.3 255.27,114.3 E20.J2 | v255.27,97.79 258.44,97.79 E20.P2
-MA11  (via drill 0.61)
  Top 0.254: 247.65,35.56 247.65,70.48 251.46,74.29 v251.46,84.45 250.82,85.09 250.82,111.76 252.09,113.03 252.09,114.3 250.82,115.57 250.82,137.16 251.46,137.79 251.46,147.95 v252.09,148.59 | 247.65,35.56 v247.65,30.48 | v251.46,12.7 250.82,13.34 250.82,18.41 257.18,24.77 257.18,26.03 247.65,35.56
  Route2 0.254: v251.46,12.7 252.73,11.43 255.91,11.43 256.54,10.79 274.95,10.79 276.86,12.7 278.13,12.7 280.67,10.16 290.83,10.16 291.46,10.79 332.11,10.79 332.74,10.16 336.55,10.16 337.19,10.79 351.15,10.79 352.43,12.06 352.43,13.34 351.15,14.61 348.62,14.61 347.98,15.24 F13.U2
  Route3 0.254: v233.68,154.31 233.68,158.11 D22.S2
  Bottom 0.254: v247.65,30.48 239.4,30.48 238.76,29.84 236.22,29.84 235.59,30.48 226.69,30.48 226.06,29.84 223.52,29.84 222.88,30.48 212.72,30.48 212.09,29.84 210.82,29.84 210.19,30.48 201.29,30.48 200.66,29.84 196.22,29.84 195.58,29.21 F25.P2 | v251.46,84.45 250.82,85.09 250.82,88.27 255.27,88.27 E20.T2 | v233.68,154.31 236.22,151.76 238.12,151.76 239.4,150.5 248.28,150.5 248.92,151.13 249.56,151.13 v252.09,148.59
-MASH  (via drill 0.61)
  Top 0.254: v400.05,140.34 400.05,165.73 398.78,167 398.78,170.81 D09.M2 | v320.68,140.97 320.68,128.91 319.4,127.63 E15.D2 319.4,126.36 320.68,125.09 320.68,113.03 321.94,111.76 E15.K2 321.94,110.49 320.68,109.22 320.68,103.5 319.4,102.23 E15.N2 319.4,100.96 319.4,97.79 320.68,96.52 320.68,87.63 321.94,86.36 E15.U2 | E18.K2 283.85,111.76 282.57,113.03 282.57,124.46 281.31,125.73 281.31,126.36 E18.D2
  Bottom 0.254: E20.U2 259.08,85.72 262.89,85.72 264.8,87.63 269.88,87.63 271.14,86.36 E19.U2 271.78,86.36 274.32,86.36 275.59,87.63 278.13,87.63 278.76,86.99 283.21,86.99 283.85,86.36 E18.U2 284.48,85.72 287.02,85.72 288.93,87.63 295.27,87.63 296.55,86.36 E17.U2 297.18,86.36 299.72,86.36 300.99,87.63 307.98,87.63 309.25,86.36 E16.U2 309.88,86.36 312.42,86.36 313.69,87.63 320.68,87.63 321.94,86.36 E15.U2 | E20.K2 259.08,111.76 263.52,111.76 264.8,113.03 265.43,113.03 266.7,111.76 271.14,111.76 E19.K2 271.78,110.49 275.59,110.49 276.86,109.22 282.57,109.22 283.85,110.49 E18.K2 284.48,111.76 287.02,111.76 288.29,113.03 295.27,113.03 296.55,111.76 E17.K2 | E20.D2 255.91,126.36 256.54,125.73 260.99,125.73 261.62,125.09 262.89,125.09 264.16,126.36 267.97,126.36 E19.D2 268.61,126.36 269.24,125.73 273.69,125.73 274.32,125.09 275.59,125.09 276.86,126.36 280.67,126.36 E18.D2 281.31,126.36 281.94,125.73 286.38,125.73 287.02,125.09 288.29,125.09 289.56,126.36 293.37,126.36 E17.D2 294,126.36 294.64,125.73 299.08,125.73 299.72,125.09 300.99,125.09 302.26,126.36 306.07,126.36 E16.D2 306.7,126.36 307.34,125.73 311.79,125.73 312.42,125.09 313.69,125.09 314.96,126.36 318.77,126.36 E15.D2 | E20.N2 255.91,102.23 260.35,102.23 261.62,103.5 262.25,103.5 263.52,102.23 267.97,102.23 E19.N2 268.61,102.23 272.42,102.23 273.69,103.5 274.95,103.5 276.23,102.23 280.67,102.23 E18.N2 281.31,102.23 285.12,102.23 286.38,103.5 287.65,103.5 288.93,102.23 293.37,102.23 E17.N2 294,102.23 298.45,102.23 299.72,103.5 300.36,103.5 302.26,101.6 306.07,101.6 E16.N2 306.7,102.23 307.98,103.5 313.06,103.5 314.32,102.23 318.77,102.23 E15.N2
  Bottom 0.254: E16.K2 309.88,111.76 314.32,111.76 315.6,113.03 316.87,113.03 318.13,111.76 321.94,111.76 E15.K2 | v400.05,140.34 375.29,140.34 374.65,140.97 v320.68,140.97
-MB00  (via drill 0.61)
  Top 0.254: v353.69,25.4 352.43,24.13 v352.43,6.98 | v234.31,5.71 227.97,5.71 227.97,12.7 225.43,15.24 v225.43,23.49
  Route2 0.254: v353.69,25.4 356.87,25.4 F12.R2 | v352.43,6.98 350.52,5.08 344.81,5.08 342.9,6.98 308.61,6.98 307.98,6.35 306.07,6.35 304.8,7.62 257.18,7.62 v255.91,6.35 | v230.5,259.72 231.14,259.08 238.76,259.08 239.4,258.44 244.47,258.44 245.75,259.72 C21.E2
  Route3 0.254: v225.43,23.49 225.43,26.67 222.25,29.84 222.25,56.52 219.07,59.69 219.07,76.83 209.55,86.36 209.55,110.49 212.72,113.66 212.72,128.91 206.38,135.25 206.38,212.09 207.65,213.36 207.65,220.34 206.38,221.61 206.38,233.04 v205.1,234.31 | v214.63,238.12 222.25,245.75 222.25,251.46 v230.5,259.72
  Bottom 0.254: v255.91,6.35 255.27,6.98 247.65,6.98 246.38,5.71 v234.31,5.71 | v205.1,234.31 207.01,236.22 212.72,236.22 v214.63,238.12
-MB01  (via drill 0.61)
  Top 0.254: v355.6,12.06 355.6,17.14 356.87,18.41 F12.T2 | v198.12,69.22 201.93,73.02 201.93,83.82 203.2,85.09 v203.2,92.07 | v229.87,228.6 231.78,230.5 v231.78,248.28 | v245.75,250.82 245.75,253.36 C21.H2
  Route2 0.254: v355.6,12.06 353.06,9.52 344.17,9.52 342.26,7.62 309.25,7.62 307.98,8.89 260.99,8.89 260.35,8.25 247.65,8.25 246.38,9.52 v235.59,9.52 | v195.58,218.44 196.85,217.17 218.44,217.17 v229.87,228.6 | v231.78,248.28 232.41,248.92 238.76,248.92 239.4,249.56 244.47,249.56 v245.75,250.82
  Route3 0.254: v235.59,9.52 227.33,17.78 224.79,17.78 224.16,17.14 222.88,17.14 222.88,17.78 196.85,43.82 196.85,67.94 v198.12,69.22 | v203.2,92.07 203.2,94.61 196.85,100.96 196.85,116.84 200.03,120.02 200.03,141.6 193.68,147.95 193.68,216.53 v195.58,218.44
-MB02  (via drill 0.61)
  Top 0.254: v370.2,65.41 369.57,66.04 v369.57,70.48
  Route2 0.254: v370.2,65.41 371.48,65.41 371.48,59.05 370.2,57.79 F11.D2 | v369.57,70.48 367.03,73.02 351.79,73.02 349.25,70.48 342.9,70.48 342.26,71.12 300.36,71.12 298.45,69.22 290.83,69.22 286.38,73.66 276.23,73.66 268.61,81.28 266.06,81.28 254,93.34 254,99.06 v242.57,110.49
  Route3 0.254: v242.57,110.49 241.3,111.76 241.3,125.09 238.12,128.27 238.12,145.41 234.95,148.59 234.95,164.47 241.3,170.81 241.3,172.72 238.12,175.89 238.12,203.84 240.66,206.38 240.66,220.98 241.3,221.61 241.3,245.11 v243.21,247.01
  Bottom 0.254: v243.21,247.01 245.75,247.01 C21.K2
-MB03  (via drill 0.61)
  Top 0.254: v3.17,85.72 3.17,59.05 1.91,57.79 F40.D2 1.91,56.52 1.91,54.61 6.35,50.16 6.35,18.41 v11.43,13.34 | v3.17,158.75 3.17,186.69 6.35,189.86 6.35,240.03 v7.62,241.3 | v17.14,250.82 15.88,252.09 15.88,262.89 19.05,266.06 19.05,278.77 24.77,284.48 24.77,287.66 25.4,288.29 25.4,319.41 | 25.4,319.41 25.4,398.15 26.67,399.42 A38.D2 | v370.2,41.27 370.84,40.64 370.84,39.37 371.48,38.73 v371.48,8.89 | 25.4,319.41 v27.3,319.41
  Route2 0.254: v3.17,158.75 v3.17,85.72 | v162.56,237.49 163.19,237.49 164.47,236.22 173.35,236.22 177.16,240.03 186.06,240.03 186.69,239.39 189.23,239.39 189.87,240.03 198.75,240.03 199.39,239.39 208.28,239.39 212.09,243.2 220.98,243.2 224.79,239.39 227.33,239.39 227.97,240.03 236.85,240.03 237.49,239.39 240.03,239.39 240.66,240.03 245.11,240.03 245.75,240.66 C21.M2
  Route3 0.254: v370.2,41.27 371.48,42.55 371.48,45.09 370.84,45.72 370.84,49.53 370.2,50.16 F11.F2
  Bottom 0.254: 8.89,242.57 v17.14,250.82 | 8.89,242.57 v7.62,241.3 | v162.56,237.49 158.12,233.04 148.59,233.04 147.96,233.68 139.06,233.68 138.43,233.04 137.16,233.04 135.89,234.31 134.62,234.31 132.08,236.85 123.19,236.85 122.56,236.22 113.67,236.22 113.03,236.85 110.49,236.85 109.86,236.22 100.97,236.22 97.16,240.03 91.44,240.03 90.81,239.39 85.09,239.39 84.45,240.03 75.56,240.03 74.93,239.39 72.39,239.39 71.75,240.03 62.87,240.03 62.23,239.39 59.69,239.39 59.05,240.03 50.16,240.03 49.53,239.39 46.99,239.39 46.35,240.03 37.47,240.03 36.83,239.39 34.29,239.39 33.66,240.03 24.77,240.03 24.13,239.39 23.5,239.39 19.68,243.2 15.24,243.2 5.71,233.68 3.81,233.68 3.17,234.31 3.17,242.57 8.89,242.57 | v371.48,8.89 349.88,8.89 347.98,6.98 347.35,6.98 346.07,8.25 333.38,8.25 332.74,7.62 309.25,7.62 307.98,8.89 307.34,8.25 261.62,8.25 260.99,7.62 247.01,7.62 246.38,6.98 221.62,6.98 220.98,6.35 206.38,6.35 205.74,5.71 180.97,5.71 179.71,4.44 147.32,4.44 146.05,5.71 144.15,5.71 142.24,3.81 83.82,3.81 81.92,5.71 19.05,5.71 v11.43,13.34 | v27.3,319.41 33.66,319.41 34.29,318.77 41.27,318.77 42.55,320.04 B37.H2
-MB04  (via drill 0.61)
  Top 0.254: v20.32,59.05 22.23,60.96 22.23,155.57 v23.5,156.84 | v48.9,168.91 50.8,170.81 50.8,208.28 53.98,211.45 53.98,216.53 | 53.98,216.53 v53.98,306.07 | 53.98,216.53 v55.88,216.53
  Route2 0.254: v224.79,234.95 223.52,236.22 v217.17,236.22 | v161.29,233.04 160.66,233.68 160.02,233.68 156.84,230.5 154.94,230.5 v151.13,226.69 | v341,107.95 342.26,106.68 346.07,106.68 347.35,105.41 E13.M2
  Route3 0.254: v360.68,102.87 361.95,101.6 361.95,80.01 364.49,77.47 364.49,65.41 365.12,64.77 365.12,58.42 368.3,55.25 368.3,46.36 369.57,45.09 F11.J2 | A38.E2 29.84,396.24 25.4,396.24 25.4,354.33 34.92,344.81 34.92,324.49 41.27,318.14 41.27,310.52 42.55,309.25 42.55,308.61 B37.M2 | v269.24,123.82 269.88,124.46 269.88,156.84 267.33,159.38 267.33,160.66 263.52,164.47 263.52,177.16 260.35,180.34 260.35,218.44 v258.44,220.34 | v255.91,222.25 254,224.16 254,229.87 v252.09,231.78
  Bottom 0.254: v360.68,102.87 353.69,102.87 351.79,104.77 347.98,104.77 E13.M2 | v20.32,59.05 13.97,59.05 10.16,55.25 5.71,55.25 5.08,54.61 F40.E2 | v23.5,156.84 32.38,156.84 39.37,163.83 43.81,163.83 v48.9,168.91 | v53.98,306.07 46.99,306.07 45.72,307.34 43.18,307.34 B37.M2 | v224.79,234.95 226.69,236.85 229.24,236.85 232.41,233.68 236.85,233.68 237.49,233.04 244.47,233.04 245.75,234.31 C21.P2 246.38,234.31 249.56,234.31 v252.09,231.78 | v217.17,236.22 217.17,233.04 212.09,233.04 211.46,233.68 205.74,233.68 205.1,233.04 199.39,233.04 198.75,233.68 189.87,233.68 189.23,233.04 186.69,233.04 186.06,233.68 177.16,233.68 176.53,233.04 173.99,233.04 173.35,233.68 164.47,233.68 163.83,233.04 v161.29,233.04 | v151.13,226.69 140.97,216.53 118.75,216.53 117.47,215.26 81.28,215.26 80.01,216.53 v55.88,216.53 | v341,107.95 339.09,109.85 329.56,109.85 328.93,109.22 328.3,109.22 324.49,113.03 318.13,113.03 317.5,113.66 314.32,113.66 313.06,112.39 304.17,112.39 300.36,116.2 291.46,116.2 290.83,115.57 289.56,115.57 287.02,118.11 285.75,118.11 285.12,118.74 278.76,118.74 278.13,119.38 275.59,119.38 274.95,118.74 274.32,118.74 v269.24,123.82 | v258.44,220.34 256.54,222.25 v255.91,222.25
-MB05  (via drill 0.61)
  Top 0.254: v23.5,207.01 24.77,208.28 24.77,220.98 25.4,221.61 25.4,287.02 v30.48,292.1 | v36.2,348.62 38.1,346.71 v38.1,295.28 | v246.38,226.06 246.38,227.97 C21.S2
  Route2 0.254: v23.5,207.01 15.24,198.75 14.61,198.75 14.61,194.31 D39.D2 | v366.39,38.1 364.49,40.01 354.96,40.01 354.33,39.37 351.79,39.37 351.15,40.01 342.26,40.01 341.63,39.37 339.09,39.37 332.74,45.72 328.3,45.72 327.02,46.99 323.85,46.99 323.21,46.36 319.4,46.36 313.06,52.7 311.15,52.7 v309.88,51.44 | v287.02,190.5 v299.72,177.8 | v113.67,208.91 120.02,215.26 147.96,215.26 149.22,214 204.47,214 206.38,212.09 220.34,212.09 221.62,213.36 225.43,213.36 v227.33,211.45 | v231.78,224.79 233.04,223.52 238.12,223.52 242.57,227.97 245.75,227.97 C21.S2
  Route3 0.254: v366.39,38.1 369.57,38.1 F11.L2 | v309.88,51.44 307.98,53.34 307.98,64.77 307.34,65.41 307.34,77.47 295.27,89.53 295.27,120.02 298.45,123.19 298.45,175.26 299.72,176.53 v299.72,177.8 | v287.02,190.5 285.75,191.77 285.75,222.88 v284.48,224.16 | v227.33,211.45 231.78,215.9 231.78,222.25 230.5,223.52 v231.78,224.79
  Bottom 0.254: v30.48,292.1 32.38,294 35.56,294 36.2,293.37 38.1,293.37 | 38.1,293.37 41.27,293.37 42.55,294.64 B37.S2 | v36.2,348.62 17.78,348.62 17.78,358.14 A39.U2 | 38.1,293.37 v38.1,295.28 | v284.48,224.16 275.59,224.16 274.95,223.52 266.06,223.52 265.43,224.16 262.89,224.16 262.25,223.52 253.37,223.52 252.73,224.16 250.19,224.16 249.56,223.52 248.92,223.52 v246.38,226.06 | v23.5,207.01 24.77,208.28 35.56,208.28 36.2,207.64 67.94,207.64 69.22,208.91 73.66,208.91 74.93,207.64 97.16,207.64 98.42,208.91 v113.67,208.91
-MB06  (via drill 0.61)
  Top 0.254: A39.J2 13.97,386.72 12.7,385.45 12.7,363.86 13.97,362.59 A39.T2 | v203.2,276.23 203.2,260.99 207.65,260.99 C24.E2 | v279.4,80.64 279.4,59.05 280.67,57.79 F18.D2 | v236.85,86.36 234.95,88.27 234.95,99.06 v233.04,100.96 | v212.72,204.47 v212.72,109.22 | v283.85,381 285.75,382.91 285.75,389.25 292.1,395.61 292.1,396.24 296.55,396.24 A17.E2
  Route2 0.254: v10.79,281.94 9.53,281.94 9.53,248.92 3.17,242.57 3.17,240.66 7.62,236.22 9.53,236.22 9.53,201.29 10.79,200.03 12.7,200.03 12.7,193.04 13.34,192.41 15.88,192.41 17.14,191.13 D39.E2 | v215.9,207.64 217.17,208.91 217.17,210.19 202.56,210.19 v201.29,211.45 | v283.85,381 282.57,379.73 275.59,379.73 274.95,379.1 270.51,379.1 269.88,379.73 262.89,379.73 262.25,379.1 253.37,379.1 252.73,379.73 250.19,379.73 246.38,375.92 237.49,375.92 236.85,376.56 227.97,376.56 227.33,375.92 224.79,375.92 220.98,379.73 213.36,379.73 207.01,373.38 203.2,373.38 200.03,376.56 191.13,376.56 184.15,369.57 178.44,369.57 v177.16,368.3 | v90.81,344.81 94.61,348.62 149.86,348.62 153.67,352.43 159.38,352.43 167.64,360.68 v170.18,360.68
  Route3 0.254: v15.88,299.09 15.88,351.79 12.7,354.97 12.7,360.05 13.97,361.31 A39.T2 | v190.5,278.77 184.15,285.12 184.15,302.26 182.88,303.53 177.8,303.53 177.8,307.34 179.07,308.61 179.07,310.52 B26.L2 179.07,311.79 177.8,313.06 177.8,327.66 174.62,330.84 174.62,356.24 | v215.9,207.64 v212.72,204.47 | v201.29,211.45 200.03,212.72 200.03,240.03 198.75,241.3 198.75,241.94 203.2,246.38 203.2,252.09 205.74,254.63 205.74,255.91 207.65,257.81 207.65,259.72 C24.E2 | v177.16,368.3 174.62,365.76 174.62,356.24 | 174.62,356.24 v170.18,360.68
  Bottom 0.254: v10.79,281.94 10.79,287.02 11.43,287.02 19.05,294.64 19.05,300.36 17.14,300.36 v15.88,299.09 | v203.2,276.23 201.29,278.13 191.13,278.13 v190.5,278.77 | v279.4,80.64 278.76,80.01 249.56,80.01 245.75,83.82 239.4,83.82 v236.85,86.36 | v233.04,100.96 231.14,102.87 226.69,102.87 220.34,109.22 v212.72,109.22 | v90.81,344.81 83.19,344.81 80.64,347.35 17.14,347.35 17.14,354.97 15.24,356.87 14.61,356.87 14.61,361.31 A39.T2
-MB07  (via drill 0.61)
  Top 0.254: v22.23,369.57 22.23,387.99 15.88,394.34 15.88,398.15 14.61,399.42 A39.D2 | v366.39,31.75 365.12,33.02 365.12,52.7 363.86,53.98 v363.86,55.25 | v354.33,62.23 354.96,62.87 354.96,65.41 355.6,66.04 355.6,74.93 v354.96,75.56 | v241.94,81.28 241.3,81.91 v241.3,138.43 | 209.55,205.74 209.55,252.09 208.28,253.36 C24.H2 | 209.55,205.74 v209.55,138.43 | v29.84,194.94 28.57,196.22 28.57,208.28 v27.3,209.55 | v194.94,209.55 195.58,208.91 v195.58,205.74 | 209.55,205.74 v207.65,205.74 | v196.85,285.75 196.85,274.96 200.03,271.78 200.03,259.08 v204.47,254.63
  Route2 0.254: v366.39,31.75 369.57,31.75 F11.N2 | v363.86,55.25 361.31,55.25 v354.33,62.23 | v207.65,205.74 v195.58,205.74 | v204.47,364.49 200.03,360.05 200.03,354.97 v201.29,354.97
  Route3 0.254: v296.55,81.91 v301.62,76.83 | v133.99,205.74 v133.99,210.82 | v201.29,354.97 200.66,354.33 200.66,341 193.68,334.01 193.68,294 196.85,290.83 v196.85,285.75
  Bottom 0.254: v22.23,369.57 26.04,365.76 29.84,365.76 A38.S2 30.48,365.76 33.02,365.76 34.29,367.03 43.18,367.03 46.99,363.22 55.88,363.22 59.69,367.03 68.58,367.03 72.39,363.22 81.28,363.22 85.09,367.03 87.63,367.03 88.27,366.4 97.16,366.4 97.79,367.03 106.68,367.03 110.49,363.22 119.38,363.22 123.19,367.03 125.73,367.03 126.36,366.4 135.25,366.4 135.89,367.03 138.43,367.03 139.06,366.4 147.96,366.4 148.59,367.03 154.94,367.03 158.12,370.21 160.66,370.21 164.47,366.4 173.35,366.4 173.99,367.03 176.53,367.03 177.16,366.4 186.06,366.4 186.69,367.03 189.23,367.03 189.87,366.4 198.75,366.4 199.39,367.03 201.93,367.03 202.56,366.4 204.47,366.4 | 204.47,366.4 211.46,366.4 212.09,367.03 214.63,367.03 215.26,366.4 224.16,366.4 224.79,367.03 227.33,367.03 227.97,366.4 236.85,366.4 237.49,367.03 240.03,367.03 240.66,366.4 249.56,366.4 250.19,367.03 252.73,367.03 253.37,366.4 262.25,366.4 262.89,367.03 265.43,367.03 266.06,366.4 274.95,366.4 275.59,367.03 278.13,367.03 278.76,366.4 287.65,366.4 288.29,367.03 290.83,367.03 292.1,365.76 296.55,365.76 A17.S2 | v354.96,75.56 354.33,74.93 349.88,74.93 349.25,75.56 344.81,75.56 343.54,76.83 321.94,76.83 321.31,76.2 314.96,76.2 314.32,75.56 302.89,75.56 v301.62,76.83 | v296.55,81.91 295.91,81.28 288.29,81.28 287.65,80.64 280.67,80.64 279.4,79.38 248.92,79.38 247.01,81.28 v241.94,81.28 | v241.3,138.43 240.66,139.06 210.19,139.06 v209.55,138.43 | v29.84,194.94 26.04,194.94 20.32,189.23 17.78,189.23 17.78,184.78 D39.H2 | v27.3,209.55 28.57,210.82 74.3,210.82 76.2,208.91 95.89,208.91 97.79,210.82 114.3,210.82 114.94,210.19 133.35,210.19 v133.99,210.82
  Bottom 0.254: v133.99,205.74 161.29,205.74 162.56,207.01 184.15,207.01 186.69,209.55 v194.94,209.55 | 204.47,366.4 v204.47,364.49 | v204.47,254.63 207.65,254.63 C24.H2
-MB08  (via drill 0.61)
  Top 0.254: v11.43,186.06 12.06,186.69 12.06,189.23 12.7,189.86 12.7,200.66 v13.34,201.29 | v165.1,240.66 165.1,219.07 v163.19,217.17 165.74,214.63 165.74,203.2 v167,201.93 | v296.55,352.43 296.55,358.14 A17.U2 296.55,359.41 296.55,361.31 v295.27,362.59 | v268.61,283.21 267.97,282.58 v267.97,274.96 | v233.04,274.96 231.78,273.69 v231.78,251.46 | v19.05,412.75 19.05,398.78 17.78,397.51 A39.E2 | v285.75,411.48 285.75,400.69 279.4,394.34 279.4,375.29 276.23,372.11 v276.23,365.76 | v242.57,53.34 241.3,54.61 241.3,79.38 v239.4,81.28 | v179.71,86.36 180.97,87.63 v180.97,200.66
  Route2 0.254: v361.95,27.94 362.58,27.3 363.86,27.3 365.12,26.03 369.57,26.03 F11.R2
  Route3 0.254: v172.72,241.3 v175.9,244.47 | v296.55,352.43 292.1,347.98 292.1,287.66 288.29,283.85 v287.65,283.85 | v147.96,410.85 v144.15,414.66 | v303.53,36.83 299.72,40.64 299.72,42.55 v291.46,50.8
